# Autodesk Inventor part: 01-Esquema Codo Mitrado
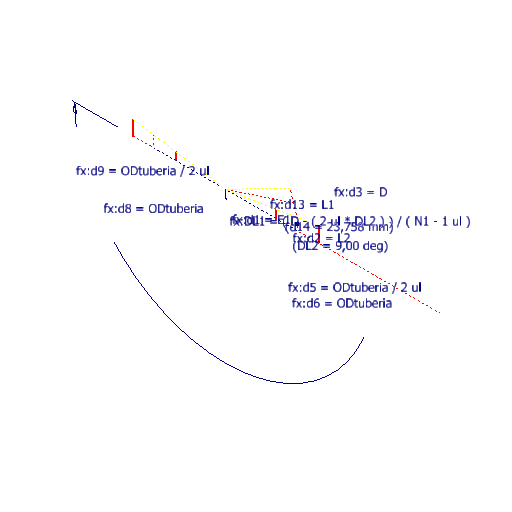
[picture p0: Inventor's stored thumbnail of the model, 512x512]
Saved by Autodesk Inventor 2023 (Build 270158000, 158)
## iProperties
Created: 2023-01
Part Number: 01-Esquema Codo Mitrado
Material: Generic
Document SubType Name: Modeling
Designer: Nelson C Agudelo A
Density: 1 g/cm^3
Appearance: Default
d1: 500,000 mm
d2: 79,192 mm
d3: 180,00 deg
d4: 300,000 mm
d5: 150,000 mm
d6: 300,000 mm
d8: 300,000 mm
d9: 150,000 mm
DL1: 18,00 deg
d13: 158,384 mm
L2: 79,192 mm
L1: 158,384 mm
Recorte: 23,758 mm
D: 180,00 deg
N1: 10,000 ul
E1: 500,000 mm
ODtuberia: 300,000 mm
DL2: 9,00 deg
d14: 23,758 mm
Author: Nelson C Agudelo A
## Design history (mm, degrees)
sketch "Sketch1"
  geometry: L1 (0, 0)-(500, 0); L2 (500, 0)-(500, 79.192); L3 (350, 0)-(350, 55.435); L4 (650, 0)-(650, 102.95); L5 (0, 0)-(650, 102.95); L6 (0, 0)-(-500, 0); L7 (-350, 0)-(-350, 55.435); L8 (-650, 0)-(-650, 102.95); L9 (-500, 0)-(-650, 0); L10 (0, 0)-(-650, 102.95); L11 (-500, 0)-(-500, 79.192); L12 (0, 0)-(451.057, 229.825); L13 (500, 79.192)-(451.057, 229.825); L14 (0, 0)-(475.528, 154.508); L15 (650, 0)-(1150, 0); L16 (500, 0)-(1000, 0); L17 (1000, 0)-(1500, 0); 1 further point
  constraints: 34 end point, 7 point on line, 5 equal length, 4 perpendicular, 3 horizontal, 2 midpoint, 2 vertical, 1 collinear, 1 horizontal alignment
  dimensions: "d1" = 500 distance of L1.start L1.end (derived); "d2" = 79.19222 distance of L1.end L2.end (derived); "d3" = 180 deg angle of L1 L6 (derived); "d5" = 150 horizontal distance of point (500, 39.596) L4.start (derived); "d6" = 300 distance of L3.start L4.start (derived); "DL2" = 9 deg angle of L5 L1 (derived); "d8" = 300 distance between parallel lines of L8 L7 (derived); "d9" = 150 distance of L6.end L8.start (derived); "DL1" = 18 deg angle of L12 L5 (derived); "d13" = 158.38444 distance of L2.end L12.end (derived); "d14" = 23.75767 vertical distance of L4.end L2.end (derived)
other parameters: "d4" = 300 (derived)
